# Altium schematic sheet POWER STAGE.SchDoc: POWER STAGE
size A3; DocumentNumber: 5; SheetNumber: 5; SheetTotal: 6
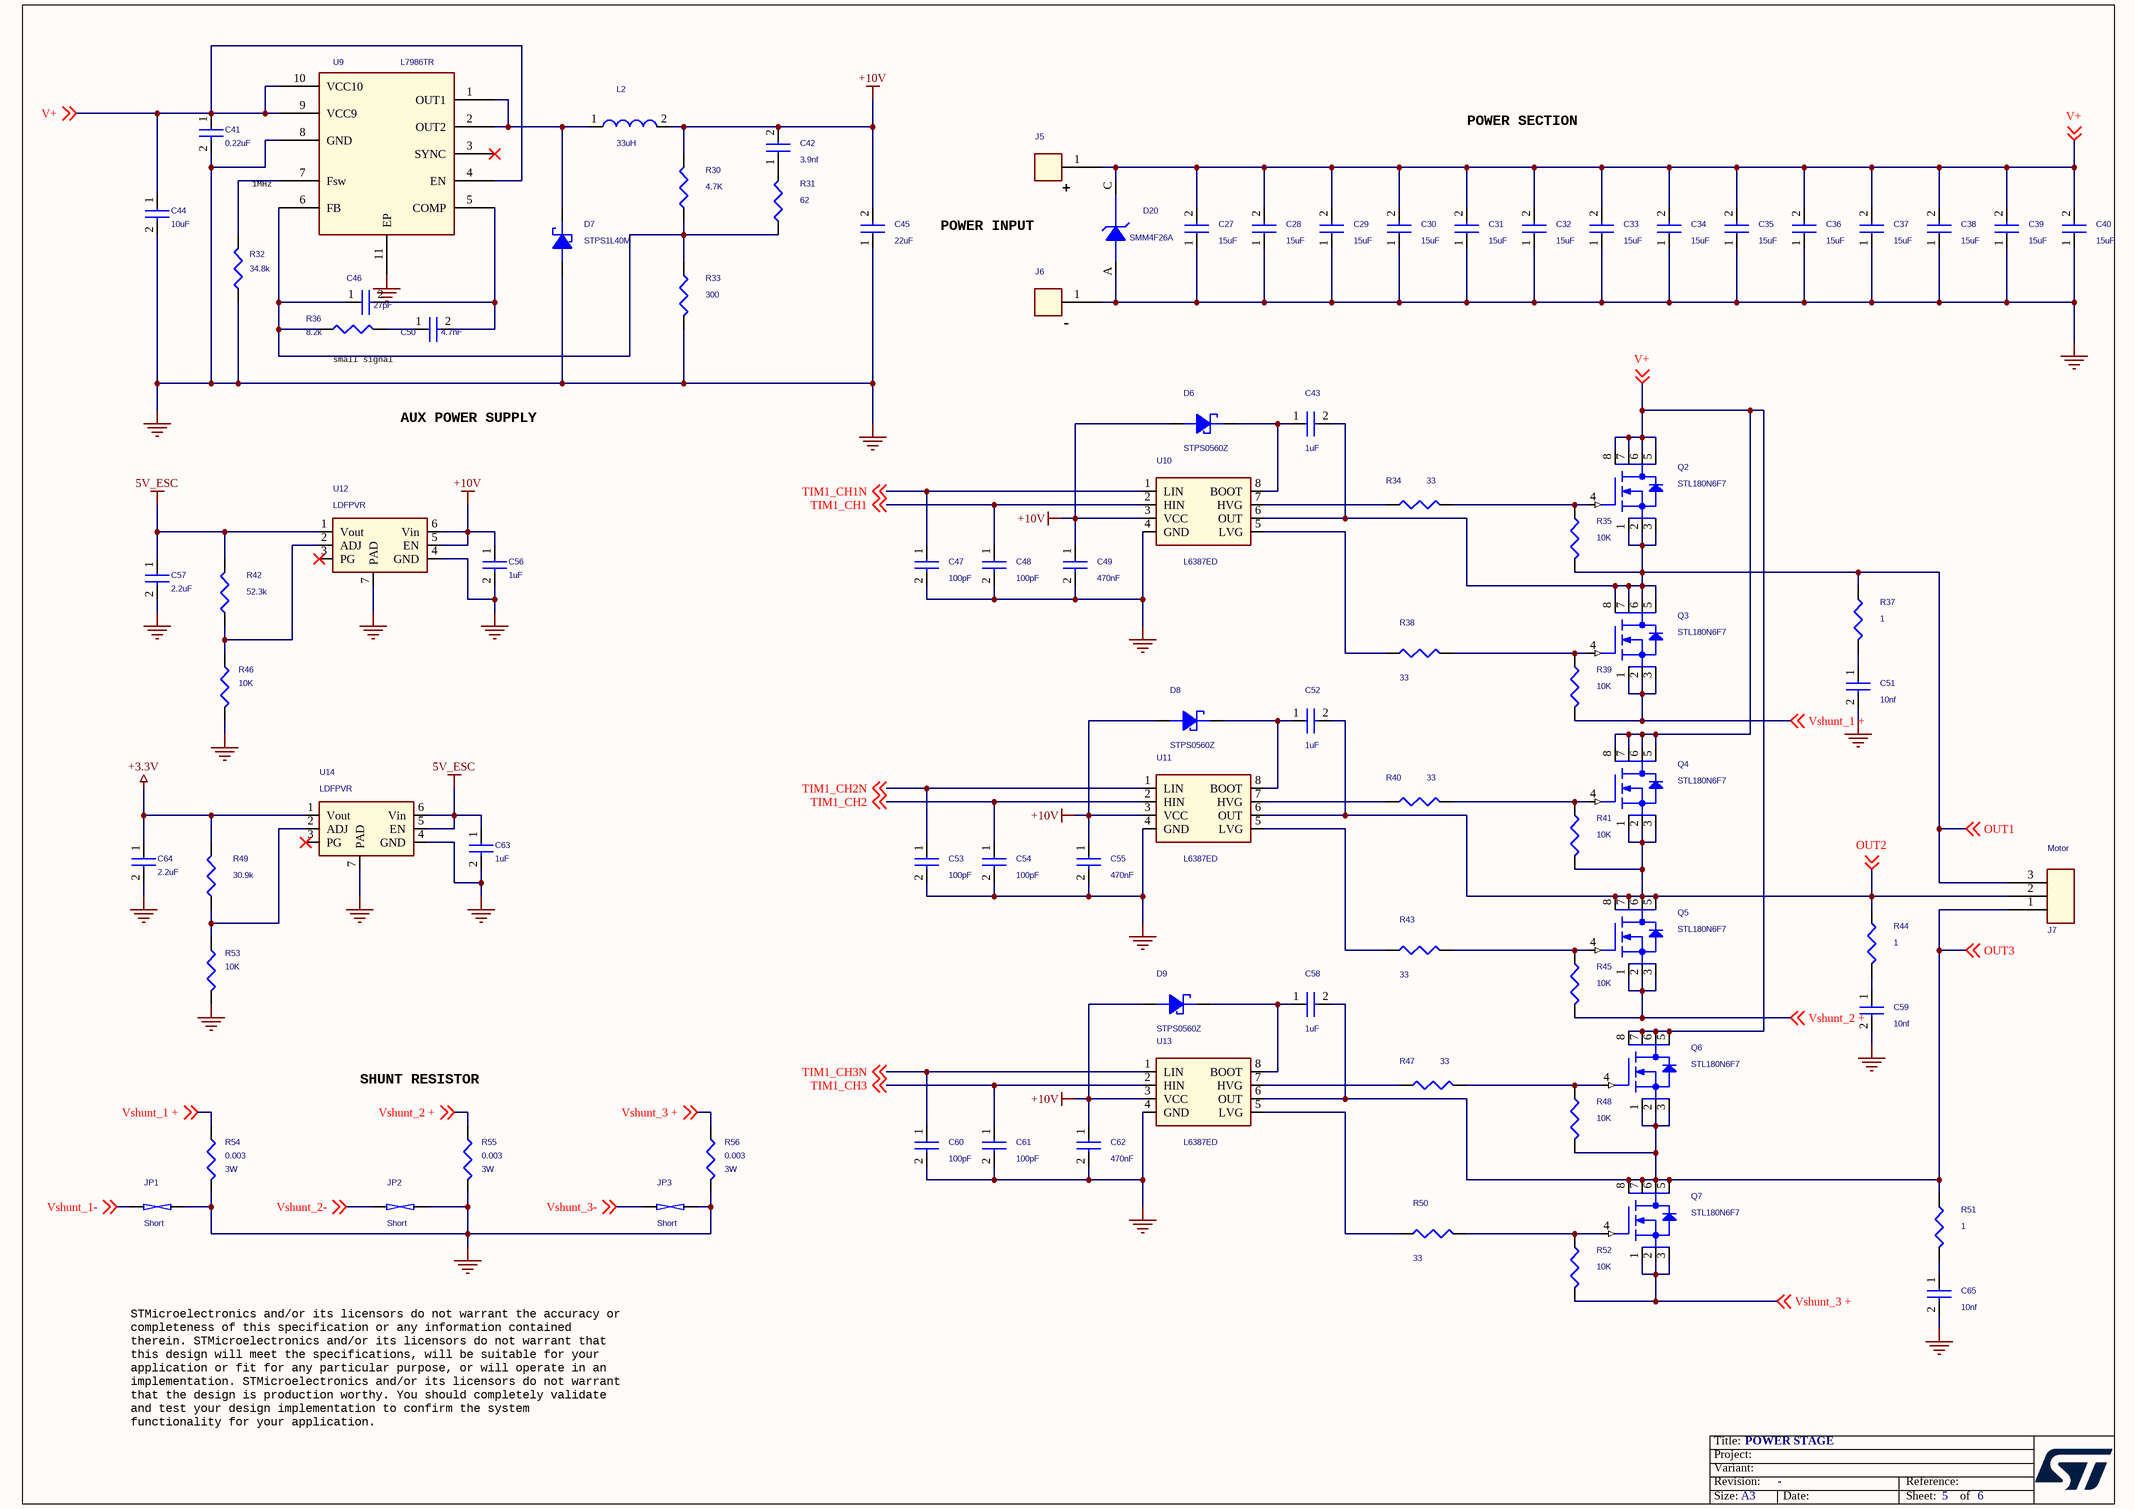
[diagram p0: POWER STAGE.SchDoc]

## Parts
C27  15uF  [C_0805_HD]
C28  15uF  [C_0805_HD]
C29  15uF  [C_0805_HD]
C30  15uF  [C_0805_HD]
C31  15uF  [C_0805_HD]
C32  15uF  [C_0805_HD]
C33  15uF  [C_0805_HD]
C34  15uF  [C_0805_HD]
C35  15uF  [C_0805_HD]
C36  15uF  [C_0805_HD]
C37  15uF  [C_0805_HD]
C38  15uF  [C_0805_HD]
C39  15uF  [C_0805_HD]
C40  15uF  [C_0805_HD]
C41  0.22uF  [C_0603_HD]
C42  3.9nf  [C_0402]
C43  1uF  [C_0603_HD]
C44  10uF  [C_1206]
C45  22uF  [C_1206]
C46  27pF  [C_0402]
C47  100pF  [C_0402]
C48  100pF  [C_0402]
C49  470nF  [C_0603_HD]
C50  4.7nF  [C_0402]
C51  10nf  [C_0603]
C52  1uF  [C_0603_HD]
C53  100pF  [C_0402]
C54  100pF  [C_0402]
C55  470nF  [C_0603_HD]
C56  1uF  [C_0402]
C57  2.2uF  [C_0402]
C58  1uF  [C_0603_HD]
C59  10nf  [C_0603]
C60  100pF  [C_0402]
C61  100pF  [C_0402]
C62  470nF  [C_0603_HD]
C63  1uF  [C_0402]
C64  2.2uF  [C_0402]
C65  10nf  [C_0603]
D6  STPS0560Z  [SOD_123]
D7  STPS1L40M  [do216-aa_stmite]
D8  STPS0560Z  [SOD_123]
D9  STPS0560Z  [SOD_123]
D20  SMM4F26A  [do216-aa-flat]
J5  CON1  [wire1_220s]  (value not drawn)
J6  CON1  [wire1_220s]  (value not drawn)
J7  Motor  [conn_motor_out]
JP1  Short  [SHORT]
JP2  Short  [SHORT]
JP3  Short  [SHORT]
L2  33uH  [ind_Coilcraft-LPS4018]
Q2  STL180N6F7  [power_flat_5x6]
Q3  STL180N6F7  [power_flat_5x6]
Q4  STL180N6F7  [power_flat_5x6]
Q5  STL180N6F7  [power_flat_5x6]
Q6  STL180N6F7  [power_flat_5x6]
Q7  STL180N6F7  [power_flat_5x6]
R30  4.7K  [R_0402]
R31  62  [R_0402]
R32  34.8k  [R_0402]
R33  300  [R_0402]
R34  33  [R_0603_HD]
R35  10K  [R_0402]
R36  8.2k  [R_0402]
R37  1  [R_0805]
R38  33  [R_0603_HD]
R39  10K  [R_0402]
R40  33  [R_0603_HD]
R41  10K  [R_0402]
R42  52.3k  [R_0402]
R43  33  [R_0603_HD]
R44  1  [R_0805]
R45  10K  [R_0402]
R46  10K  [R_0402]
R47  33  [R_0603_HD]
R48  10K  [R_0402]
R49  30.9k  [R_0402]
R50  33  [R_0603_HD]
R51  1  [R_0805]
R52  10K  [R_0402]
R53  10K  [R_0402]
R54  0.003  Rated Power: 3W  [resc635x300x60l193n]
R55  0.003  Rated Power: 3W  [resc635x300x60l193n]
R56  0.003  Rated Power: 3W  [resc635x300x60l193n]
U9  L7986TR  [son11p50_300x300x100l40x24t2-1]
U10  L6387ED  [SOIC8P127_490X600X175L83X42N]
U11  L6387ED  [SOIC8P127_490X600X175L83X42N]
U12  LDFPVR  [son7p65_200x200x100l25x30t18-1]
U13  L6387ED  [SOIC8P127_490X600X175L83X42N]
U14  LDFPVR  [son7p65_200x200x100l25x30t18-1]

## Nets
5V_ESC: C57.1 C63.1 R42.2 U12.1(Vout) U14.5(EN) U14.6(Vin)
+3.3V: C64.1 R49.2 U14.1(Vout)
+10V: C42.2 C45.2 C49.1 C55.1 C56.1 C62.1 D6.A D8.A D9.A L2.2 R30.1 U10.3(VCC) U11.3(VCC) U12.5(EN) U12.6(Vin) U13.3(VCC)
GND: C27.1 C28.1 C29.1 C30.1 C31.1 C32.1 C33.1 C34.1 C35.1 C36.1 C37.1 C38.1 C39.1 C40.1 C41.2 C44.2 C45.1 C47.2 C48.2 C49.2 C51.2 C53.2 C54.2 C55.2 C56.2 C57.2 C59.2 C60.2 C61.2 C62.2 C63.2 C64.2 C65.2 D7.A D20.A J6.1 JP1.2 JP2.2 JP3.2 R32.2 R33.1 R46.2 R53.2 R54.2 R55.2 R56.2 U9.8(GND) U9.11(EP) U10.4(GND) U11.4(GND) U12.4(GND) U12.7(PAD) U13.4(GND) U14.4(GND) U14.7(PAD)
OUT1: C43.2 J7.3 Q2.1(S1) Q2.2(S2) Q2.3(S3) Q3.5(D) Q3.6(D6) Q3.7(D7) Q3.8(D8) R35.2 R37.1 U10.6(OUT) ; off-sheet OUT1
OUT2: C52.2 J7.2 Q4.1(S1) Q4.2(S2) Q4.3(S3) Q5.5(D) Q5.6(D6) Q5.7(D7) Q5.8(D8) R41.2 R44.1 U11.6(OUT) ; off-sheet OUT2
OUT3: C58.2 J7.1 Q6.1(S1) Q6.2(S2) Q6.3(S3) Q7.5(D) Q7.6(D6) Q7.7(D7) Q7.8(D8) R48.2 R51.1 U13.6(OUT) ; off-sheet OUT3
TIM1_CH1: C48.1 U10.2(HIN) ; off-sheet TIM1_CH1
TIM1_CH1N: C47.1 U10.1(LIN) ; off-sheet TIM1_CH1N
TIM1_CH2: C54.1 U11.2(HIN) ; off-sheet TIM1_CH2
TIM1_CH2N: C53.1 U11.1(LIN) ; off-sheet TIM1_CH2N
TIM1_CH3: C61.1 U13.2(HIN) ; off-sheet TIM1_CH3
TIM1_CH3N: C60.1 U13.1(LIN) ; off-sheet TIM1_CH3N
V+: C27.2 C28.2 C29.2 C30.2 C31.2 C32.2 C33.2 C34.2 C35.2 C36.2 C37.2 C38.2 C39.2 C40.2 C41.1 C44.1 D20.C J5.1 Q2.5(D) Q2.6(D6) Q2.7(D7) Q2.8(D8) Q4.5(D) Q4.6(D6) Q4.7(D7) Q4.8(D8) Q6.5(D) Q6.6(D6) Q6.7(D7) Q6.8(D8) U9.4(EN) U9.9(VCC9) U9.10(VCC10) ; off-sheet V+
Vshunt_1 +: Q3.1(S1) Q3.2(S2) Q3.3(S3) R39.2 R54.1 ; off-sheet Vshunt_1 +
Vshunt_1-: JP1.1 ; off-sheet Vshunt_1-
Vshunt_2 +: Q5.1(S1) Q5.2(S2) Q5.3(S3) R45.2 R55.1 ; off-sheet Vshunt_2 +
Vshunt_2-: JP2.1 ; off-sheet Vshunt_2-
Vshunt_3 +: Q7.1(S1) Q7.2(S2) Q7.3(S3) R52.2 R56.1 ; off-sheet Vshunt_3 +
Vshunt_3-: JP3.1 ; off-sheet Vshunt_3-
NetC42_1: C42.1 R31.1
NetC43_1: C43.1 D6.C U10.8(BOOT)
NetC46_1: C46.1 R30.2 R31.2 R33.2 R36.2 U9.6(FB)
NetC46_2: C46.2 C50.2 U9.5(COMP)
NetC50_1: C50.1 R36.1
NetC51_1: C51.1 R37.2
NetC52_1: C52.1 D8.C U11.8(BOOT)
NetC58_1: C58.1 D9.C U13.8(BOOT)
NetC59_1: C59.1 R44.2
NetC65_1: C65.1 R51.2
NetD7_C: D7.C L2.1 U9.1(OUT1) U9.2(OUT2)
NetQ2_4: Q2.4(G) R34.2 R35.1
NetQ3_4: Q3.4(G) R38.2 R39.1
NetQ4_4: Q4.4(G) R40.2 R41.1
NetQ5_4: Q5.4(G) R43.2 R45.1
NetQ6_4: Q6.4(G) R47.2 R48.1
NetQ7_4: Q7.4(G) R50.2 R52.1
NetR32_1: R32.1 U9.7(Fsw)
NetR34_1: R34.1 U10.7(HVG)
NetR38_1: R38.1 U10.5(LVG)
NetR40_1: R40.1 U11.7(HVG)
NetR42_1: R42.1 R46.1 U12.2(ADJ)
NetR43_1: R43.1 U11.5(LVG)
NetR47_1: R47.1 U13.7(HVG)
NetR49_1: R49.1 R53.1 U14.2(ADJ)
NetR50_1: R50.1 U13.5(LVG)

Not connected (* = marked no-connect by the designer): U9 3(SYNC)*; U12 3(PG)*; U14 3(PG)*

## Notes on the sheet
- POWER SECTION
- 1MHz
- POWER INPUT
- (near J5) +
- (near R36) small signal
- (near J6) -
- AUX POWER SUPPLY
- (near R55) SHUNT RESISTOR
- STMicroelectronics and/or its licensors do not warrant the accuracy or
  completeness of this specification or any information contained
  therein. STMicroelectronics and/or its licensors do not warrant that
  this design will meet the specifications, will be suitable for your
  application or fit for any particular purpose, or will operate in an
  implementation. STMicroelectronics and/or its licensors do not warrant
  that the design is production worthy. You should completely validate
  and test your design implementation to confirm the system
  functionality for your application.

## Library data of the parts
C27-C40 = CAP_Dup1: CAP CER 15UF 35V X5R 0805; PART_NUMBER: TMP-773; Manufacturer: TDK Corporation; Manufacturer PN: C2012X5R1V156M125AC; Dielectric Type: Capacitors; Tolerance: 20%; CLASS: DISCRETE
C41 = CAP_Dup1: CAP CER 0.22UF 50V X7R 0603; Manufacturer PN: CGA3E3X7R1H224K080AD; Manufacturer: TDK Corporation; PART_NUMBER: TMP-138; CLASS: DISCRETE; Tolerance: 10%; Dielectric Type: Capacitors
C42 = CAP_Dup1: CAP CER 3900PF 16V X7R 0402; Manufacturer PN: C0402C392K4RAC7867; Manufacturer: KEMET; PART_NUMBER: TMP-419; CLASS: DISCRETE; Tolerance: 10%; Dielectric Type: Capacitors
C43 C52 C58 = CAP_Dup1: CAP CER 1UF 25V X7R 0603; PART_NUMBER: TMP-446; Manufacturer: Wurth Electronics Inc.; Manufacturer PN: 885012206076; Dielectric Type: Capacitors; Tolerance: 10%; CLASS: DISCRETE
C44 = CAP_Dup1: CAP CER 10UF 50V X7R 1206; Manufacturer PN: CL31B106KBHNNNE; Manufacturer: Samsung Electro-Mechanics America, Inc.; PART_NUMBER: CAP-00000016; CLASS: DISCRETE; Tolerance: 10%; Dielectric Type: Capacitors
C45 = CAP_Dup1: CAP CER 22UF 25V X5R 1206; Manufacturer PN: GRT31CR61E226ME01L; Manufacturer: Murata Electronics North America; PART_NUMBER: TMP-421; CLASS: DISCRETE; Tolerance: 20%; Dielectric Type: Capacitors
C46 = CAP_Dup1: CAP CER 27PF 25V C0G/NP0 0402; Manufacturer PN: GRM1555C1E270JA01D; Manufacturer: Murata Electronics North America; PART_NUMBER: TMP-416; CLASS: DISCRETE; Tolerance: 5%; Temperature Coefficient: C0G, NP0; Dielectric Type: Capacitors
C47 C48 C53 C54 C60 C61 = CAP_Dup1: CAP CER 100PF 25V X7R 0402; PART_NUMBER: TMP-426; Manufacturer: Wurth Electronics Inc.; Manufacturer PN: 885012205038; Dielectric Type: Capacitors; Tolerance: 10%; CLASS: DISCRETE
C49 C55 C62 = CAP_Dup1: CAP CER 0.47UF 25V X7R 0603; PART_NUMBER: TMP-428; Manufacturer: Wurth Electronics Inc.; Manufacturer PN: 885012206075; Dielectric Type: Capacitors; Tolerance: 10%; CLASS: DISCRETE
C50 = CAP_Dup1: CAP CER 4700PF 16V X7R 0402; Manufacturer PN: 885012205029; Manufacturer: Wurth Electronics Inc.; PART_NUMBER: TMP-417; CLASS: DISCRETE; Tolerance: 10%; Dielectric Type: Capacitors
C51 C59 C65 = CAP_Dup1: CAP CER 10000PF 100V X7R 0603; PART_NUMBER: CAP-00000040; Manufacturer: TDK Corporation; Manufacturer PN: C1608X7R2A103M080AA; Dielectric Type: Capacitors; Tolerance: 20%; CLASS: DISCRETE
C56 C63 = CAP_Dup1: CAP CER 1UF 25V X5R 0402; Manufacturer PN: GRM155R61E105KA12D; Manufacturer: Murata Electronics North America; PART_NUMBER: CAP-00000006; CLASS: DISCRETE; Tolerance: 10%; Dielectric Type: Capacitors
C57 C64 = CAP_Dup1: CAP CER 2.2UF 10V X5R 0402; PART_NUMBER: TMP-449; Manufacturer: Wurth Electronics Inc.; Manufacturer PN: 885012105013; Dielectric Type: Capacitors; Tolerance: 20%; CLASS: DISCRETE
D6 D8 D9 = DIODE_SCHOTTKY_0: DIODE SCHOTTKY 60V 500MA SOD123; Manufacturer: STMicroelectronics; PART_NUMBER: TMP-373; CLASS: DISCRETE; Rated Voltage: 530mV @ 500mA
D7 = DIODE_SCHOTTKY_0: DIODE SCHOTTKY 40V 1A STMITE; PART_NUMBER: TMP-372; Manufacturer: STMicroelectronics; Rated Voltage: 460mV @ 1A; CLASS: DISCRETE
D20 = DIODE_TRANSIL_UNI_0: TVS DIODE 26VWM 53.5VC DO222AA; Manufacturer PN: SMM4F26A-TR; Manufacturer: STMicroelectronics; PART_NUMBER: TMP-376; CLASS: DISCRETE
J5 J6 = CON1: SOLDER PADS
J7 = CON3: SOLDER PADS
JP1-JP3 = SHORT: 2 PIN SHORTED TO CONNECT DIFFERENT NETS; PART_NUMBER: TMP-442; CLASS: DISCRETE
L2 = IND: Fixed Inductors LPS4018 Low Profile 33uH 0.8A 20% SMD; Manufacturer PN: LPS4018-333MRB; Manufacturer: Coilcraft; PART_NUMBER: TMP-377; CLASS: DISCRETE
Q2-Q7 = MOSFET_N_DIODE_SSSGDDDD: N-channel 60 V, 1.9 mO typ., 120 A STripFET™ F7; PART_NUMBER: TMP-772; Manufacturer: STMicroelectronics; CLASS: DISCRETE; Rated Voltage: 60V
R30 = RES: RES SMD 4.7K OHM 1% 1/16W 0402; Manufacturer PN: CRG0402F4K7; Manufacturer: TE Connectivity Passive Product; PART_NUMBER: TMP-403; CLASS: DISCRETE; Rated Power: 0.063W, 1/16W; Temperature Coefficient: 100ppm/C
R31 = RES: RES SMD 62 OHM 1% 1/16W 0402; Manufacturer PN: RC0402FR-0762RL; Manufacturer: Yageo; PART_NUMBER: TMP-420; CLASS: DISCRETE; Rated Power: 0.063W, 1/16W; Temperature Coefficient: 100ppm/C
R32 = RES: RES SMD 34.8K OHM 1% 1/16W 0402; Manufacturer PN: RC0402FR-0734K8L; Manufacturer: Yageo; PART_NUMBER: TMP-415; CLASS: DISCRETE; Rated Power: 0.063W, 1/16W; Temperature Coefficient: 100ppm/C
R33 = RES: RES SMD 300 OHM 1% 1/16W 0402; PART_NUMBER: TMP-418; Manufacturer: Yageo; Manufacturer PN: RC0402FR-07300RL; Temperature Coefficient: 100ppm/C; Rated Power: 0.063W, 1/16W; CLASS: DISCRETE
R34 R40 = RES: RES SMD 33 OHM 1% 1/10W 0603; Manufacturer PN: 9C06031A33R0FKHFT; Manufacturer: Yageo; PART_NUMBER: TMP-266; CLASS: DISCRETE; Rated Power: 0.1W, 1/10W; Temperature Coefficient: 100ppm/C
R35 R39 R41 R45 = RES: RES SMD 10K OHM 1% 1/16W 0402; Manufacturer PN: RC0402FR-0710KL; Manufacturer: Yageo; PART_NUMBER: TMP-396; CLASS: DISCRETE; Rated Power: 0.063W, 1/16W; Temperature Coefficient: 100ppm/C
R36 = RES: RES SMD 8.2K OHM 5% 1/16W 0402; Manufacturer PN: RC0402JR-078K2L; Manufacturer: Yageo; PART_NUMBER: RES-00000047; CLASS: DISCRETE; Rated Power: 0.063W, 1/16W; Temperature Coefficient: 100ppm/C
R37 R44 R51 = RES: RES SMD 1 OHM 5% 1/8W 0805; PART_NUMBER: TMP-430; Manufacturer: Panasonic Electronic Components; Manufacturer PN: ERJ-6GEYJ1R0V; Temperature Coefficient: -100/ +600ppm/C; Rated Power: 0.125W, 1/8W; CLASS: DISCRETE
R38 R43 R47 R50 = RES: RES SMD 33 OHM 1% 1/10W 0603; PART_NUMBER: TMP-266; Manufacturer: Yageo; Manufacturer PN: 9C06031A33R0FKHFT; Temperature Coefficient: 100ppm/C; Rated Power: 0.1W, 1/10W; CLASS: DISCRETE
R42 = RES: RES SMD 52.3K OHM 1% 1/16W 0402; Manufacturer PN: RC1005F5232CS; Manufacturer: Samsung Electro-Mechanics; PART_NUMBER: TMP-447; CLASS: DISCRETE; Rated Power: 0.063W, 1/16W; Temperature Coefficient: 100ppm/C
R46 = RES: RES SMD 10K OHM 1% 1/16W 0402; PART_NUMBER: TMP-396; Manufacturer: Yageo; Manufacturer PN: RC0402FR-0710KL; CLASS: DISCRETE; Rated Power: 0.063W, 1/16W; Temperature Coefficient: 100ppm/C
R48 R52 R53 = RES: RES SMD 10K OHM 1% 1/16W 0402; PART_NUMBER: TMP-396; Manufacturer: Yageo; Manufacturer PN: RC0402FR-0710KL; Temperature Coefficient: 100ppm/C; Rated Power: 0.063W, 1/16W; CLASS: DISCRETE
R49 = RES: RES SMD 30.9K OHM 1% 1/10W 0402; PART_NUMBER: TMP-448; Manufacturer: Panasonic Electronic Components; Manufacturer PN: ERJ-2RKF3092X; Temperature Coefficient: 100ppm/C; Rated Power: 0.1W, 1/10W; CLASS: DISCRETE
R54 R56 = RES: RES 0.003 OHM 1% 3W 2512; PART_NUMBER: TMP-766; Manufacturer: TE Connectivity Passive Product; Manufacturer PN: TLR3A30DR003FTDG; Temperature Coefficient: 50ppm/C; CLASS: DISCRETE
R55 = RES: RES 0.003 OHM 1% 3W 2512; Manufacturer PN: TLR3A30DR003FTDG; Manufacturer: TE Connectivity Passive Product; PART_NUMBER: TMP-766; CLASS: DISCRETE; Temperature Coefficient: 50ppm/C
U9 = L7986TR: IC REG BUCK ADJ 3A 10VDFPN; Manufacturer: STMicroelectronics; PART_NUMBER: TMP-362
U10 = L6387E: IC DRIVER HI/LO SIDE HV 8-SOIC; Manufacturer: STMicroelectronics; PART_NUMBER: TMP-367; Supply Voltage: 17V (Max)
U11 U13 = L6387E: IC DRIVER HI/LO SIDE HV 8-SOIC; PART_NUMBER: TMP-367; Manufacturer: STMicroelectronics; Supply Voltage: 17V (Max)
U12 = LDFPxR: IC REG LINEAR POS ADJ 1A 6DFN; PART_NUMBER: TMP-450; Manufacturer: STMicroelectronics
U14 = LDFPxR: IC REG LINEAR POS ADJ 1A 6DFN; Manufacturer: STMicroelectronics; PART_NUMBER: TMP-450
